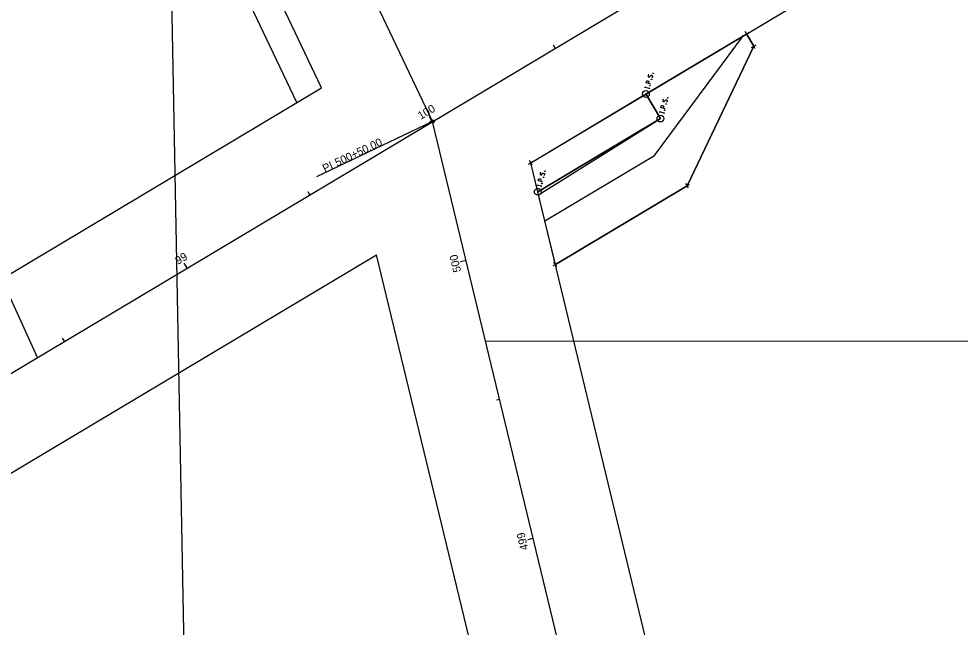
# Model space of a CAD drawing. Extents: x 2351593 to 2354159, y 766293 to 768001.
# Drawn here: x 2352271.1 to 2352600.5, y 766754.1 to 766966.8 of the extents above; entities that cross this region are included whole.
import ezdxf

# ---------------------------------------------------------------- set-up
doc = ezdxf.new("R2010")
doc.units = 0
for name, color, linetype in [('BD_X_Building', 7, 'Continuous'), ('PV_X_COP', 7, 'Continuous'), ('PV_X_Curb', 7, 'Continuous'), ('PV_X_Walk', 7, 'Continuous'), ('RD_X_Fence', 7, 'Continuous'), ('RD_X_Misc_Items', 7, 'Continuous'), ('SV_P_Mon_Cells_Set', 7, 'Continuous'), ('SV_X_Break_Lines', 7, 'Continuous'), ('SV_X_Mon_Cells_Found', 7, 'Continuous'), ('SV_X_Random_Point', 7, 'Continuous'), ('SV_X_Shot_Marker', 7, 'Continuous'), ('UT_X_Water_Cells', 7, 'Continuous'), ('VG_X_Cells', 7, 'Continuous'), ('VG_X_Flower_Bed', 7, 'Continuous'), ('VG_X_Shrub_Line_Lt', 7, 'Continuous')]:
    doc.layers.add(name, color=color, linetype=linetype)

msp = doc.modelspace()

# ---------------------------------------------------------------- linework, layer by layer
at = {"layer": 'BD_X_Building'}
for p, q in [((2352526.18, 766960.69), (2352525.21, 766962.31)), ((2352524.88, 766961.02), (2352526.5, 766961.99)), ((2352527.45, 766956.73), (2352529.07, 766957.69)), ((2352528.74, 766956.4), (2352527.77, 766958.02)), ((2352449.41, 766915.98), (2352451.03, 766916.95)), ((2352450.7, 766915.66), (2352449.73, 766917.28)), ((2352504.17, 766907.91), (2352505.8, 766908.87)), ((2352505.47, 766907.58), (2352504.5, 766909.2)), ((2352458.03, 766880.37), (2352459.65, 766881.33)), ((2352459.32, 766880.04), (2352458.35, 766881.66))]:
    msp.add_line(p, q, dxfattribs=at)
at = {"layer": 'PV_X_COP'}
for p, q in [((2352277.6, 766848.4), (2352192.4, 767035.46)), ((2352434.4, 766854.25), (2352921.95, 766853.61))]:
    msp.add_line(p, q, dxfattribs=at)
at = {"layer": 'PV_X_Curb'}
msp.add_line((2352337.69, 766292.88), (2352321.61, 767128.88), dxfattribs=at)
at = {"layer": 'PV_X_Walk'}
msp.add_line((2352415.86, 766930.9), (2352375.23, 766911.56), dxfattribs=at)
msp.add_circle((2352415.86, 766930.9), 0.6, dxfattribs=at)
at = {"layer": 'RD_X_Fence'}
for p, q in [((2352450.22, 766916.47), (2352490.49, 766940.49)), ((2352490.49, 766940.49), (2352495.61, 766931.91)), ((2352495.61, 766931.91), (2352452.68, 766906.29)), ((2352452.68, 766906.29), (2352450.22, 766916.47))]:
    msp.add_line(p, q, dxfattribs=at)
at = {"layer": 'RD_X_Misc_Items'}
for p, q in [((2352450.22, 766916.47), (2354158.95, 767936.09)), ((2352377.03, 766942.67), (2352291.74, 767121.83)), ((2351599.99, 766478.99), (2352377.03, 766942.67)), ((2352567.24, 766432.73), (2352450.22, 766916.47)), ((2352570.31, 766420.05), (2352450.22, 766916.47)), ((2351632.95, 766428.79), (2352396.27, 766884.28)), ((2352508.92, 766418.63), (2352396.27, 766884.28))]:
    msp.add_line(p, q, dxfattribs=at)
at = {"layer": 'SV_P_Mon_Cells_Set'}
for p, q in [((2352458.8, 766956.52), (2352458.18, 766957.55)), ((2352415.86, 766930.9), (2352414.84, 766932.62)), ((2352415.86, 766930.9), (2352414.69, 766930.62)), ((2352372.92, 766905.28), (2352372.31, 766906.31)), ((2352329.99, 766879.66), (2352328.96, 766881.38)), ((2352427.62, 766882.3), (2352425.67, 766881.83)), ((2352287.05, 766854.04), (2352286.43, 766855.07)), ((2352439.37, 766833.7), (2352438.21, 766833.42)), ((2352451.13, 766785.11), (2352449.19, 766784.64))]:
    msp.add_line(p, q, dxfattribs=at)
at = {"layer": 'SV_X_Break_Lines'}
msp.add_line((2352415.86, 766930.9), (2352375.23, 766911.56), dxfattribs=at)
msp.add_circle((2352415.86, 766930.9), 0.6, dxfattribs=at)
at = {"layer": 'SV_X_Mon_Cells_Found'}
for p, q in [((2351616.47, 766453.89), (2354143.58, 767961.85)), ((2352415.86, 766930.9), (2352321.61, 767128.88)), ((2352538.08, 766425.68), (2352415.86, 766930.9))]:
    msp.add_line(p, q, dxfattribs=at)
at = {"layer": 'SV_X_Random_Point'}
for p, q in [((2352528.26, 766957.21), (2352525.69, 766961.5)), ((2352504.98, 766908.39), (2352528.26, 766957.21)), ((2352458.83, 766880.85), (2352504.98, 766908.39))]:
    msp.add_line(p, q, dxfattribs=at)
at = {"layer": 'SV_X_Shot_Marker'}
for p, q in [((2352415.86, 766930.9), (2352414.84, 766932.62)), ((2352329.99, 766879.66), (2352329.37, 766880.69)), ((2352427.62, 766882.3), (2352425.67, 766881.83)), ((2352451.13, 766785.11), (2352449.96, 766784.82))]:
    msp.add_line(p, q, dxfattribs=at)
at = {"layer": 'UT_X_Water_Cells'}
for p, q in [((2352368.41, 766937.52), (2352281.78, 767119.48)), ((2352493.5, 766919), (2352524.71, 766960.92)), ((2352455.14, 766896.11), (2352493.5, 766919))]:
    msp.add_line(p, q, dxfattribs=at)
at = {"layer": 'VG_X_Cells'}
for p, q in [((2352495.61, 766931.91), (2352490.49, 766940.49)), ((2352452.68, 766906.29), (2352495.61, 766931.91))]:
    msp.add_line(p, q, dxfattribs=at)
at = {"layer": 'VG_X_Flower_Bed'}
for p, q in [((2352490.49, 766940.49), (2352525.69, 766961.5)), ((2352525.69, 766961.5), (2352528.26, 766957.21)), ((2352528.26, 766957.21), (2352504.98, 766908.39)), ((2352495.61, 766931.91), (2352490.49, 766940.49)), ((2352452.93, 766905.27), (2352495.61, 766931.91)), ((2352504.98, 766908.39), (2352458.84, 766880.85)), ((2352458.84, 766880.85), (2352452.93, 766905.27))]:
    msp.add_line(p, q, dxfattribs=at)
at = {"layer": 'VG_X_Shrub_Line_Lt'}
for points in [[(2352491.48, 766947.23), (2352491.45, 766947.21), (2352491.41, 766947.19), (2352491.35, 766947.1), (2352491.3, 766946.99), (2352491.28, 766946.9), (2352491.27, 766946.87), (2352491.27, 766946.72), (2352491.31, 766946.59), (2352491.39, 766946.49), (2352491.48, 766946.44), (2352491.56, 766946.42), (2352491.66, 766946.42), (2352491.77, 766946.48), (2352492.28, 766946.98), (2352492.35, 766947.02), (2352492.4, 766947.03), (2352492.48, 766947.03), (2352492.55, 766947.01), (2352492.62, 766946.98), (2352492.67, 766946.96), (2352492.72, 766946.92), (2352492.77, 766946.89), (2352492.8, 766946.86), (2352492.83, 766946.82), (2352492.84, 766946.78), (2352492.86, 766946.73), (2352492.86, 766946.7), (2352492.85, 766946.6), (2352492.81, 766946.45), (2352492.76, 766946.36), (2352492.64, 766946.24), (2352492.55, 766946.17)], [(2352492.91, 766947.71), (2352492.92, 766947.76), (2352492.96, 766947.79), (2352493.01, 766947.81), (2352493.07, 766947.79), (2352493.11, 766947.75), (2352493.13, 766947.71), (2352493.12, 766947.65), (2352493.08, 766947.63), (2352493.03, 766947.61), (2352492.97, 766947.62), (2352492.93, 766947.67), (2352492.91, 766947.71)], [(2352490.2, 766942.65), (2352490.29, 766942.99)], [(2352491.8, 766942.43), (2352490.25, 766942.82)], [(2352492.18, 766943.95), (2352490.63, 766944.34), (2352490.76, 766944.85), (2352490.78, 766944.9), (2352490.83, 766944.97), (2352490.86, 766945), (2352490.89, 766945.02), (2352490.96, 766945.05), (2352491.03, 766945.06), (2352491.14, 766945.06), (2352491.28, 766945.02), (2352491.33, 766945), (2352491.4, 766944.96), (2352491.47, 766944.9), (2352491.5, 766944.85), (2352491.51, 766944.81), (2352491.53, 766944.75), (2352491.52, 766944.66), (2352491.39, 766944.15)], [(2352491.75, 766942.26), (2352491.84, 766942.6)], [(2352491.82, 766943.41), (2352491.84, 766943.46), (2352491.87, 766943.49), (2352491.93, 766943.51), (2352491.99, 766943.49), (2352492.03, 766943.45), (2352492.05, 766943.41), (2352492.03, 766943.36), (2352492, 766943.33), (2352491.94, 766943.31), (2352491.88, 766943.33), (2352491.84, 766943.37), (2352491.82, 766943.41)], [(2352492.37, 766945.59), (2352492.39, 766945.64), (2352492.42, 766945.67), (2352492.48, 766945.69), (2352492.54, 766945.67), (2352492.58, 766945.63), (2352492.6, 766945.59), (2352492.58, 766945.54), (2352492.55, 766945.51), (2352492.49, 766945.49), (2352492.43, 766945.51), (2352492.39, 766945.55), (2352492.37, 766945.59)], [(2352498.03, 766939.12), (2352498.05, 766939.17), (2352498.08, 766939.2), (2352498.14, 766939.22), (2352498.2, 766939.2), (2352498.24, 766939.16), (2352498.25, 766939.12), (2352498.24, 766939.07), (2352498.21, 766939.04), (2352498.15, 766939.02), (2352498.09, 766939.04), (2352498.05, 766939.08), (2352498.03, 766939.12)], [(2352497.3, 766935.36), (2352495.75, 766935.75), (2352495.88, 766936.26), (2352495.91, 766936.31), (2352495.95, 766936.38), (2352495.98, 766936.41), (2352496.02, 766936.43), (2352496.09, 766936.46), (2352496.16, 766936.48), (2352496.26, 766936.47), (2352496.41, 766936.44), (2352496.45, 766936.41), (2352496.52, 766936.37), (2352496.6, 766936.31), (2352496.62, 766936.26), (2352496.64, 766936.22), (2352496.65, 766936.16), (2352496.64, 766936.07), (2352496.51, 766935.56)], [(2352496.6, 766938.64), (2352496.57, 766938.62), (2352496.54, 766938.6), (2352496.48, 766938.51), (2352496.42, 766938.4), (2352496.4, 766938.31), (2352496.39, 766938.28), (2352496.39, 766938.13), (2352496.44, 766938), (2352496.52, 766937.9), (2352496.61, 766937.85), (2352496.68, 766937.83), (2352496.79, 766937.83), (2352496.89, 766937.89), (2352497.41, 766938.39), (2352497.47, 766938.43), (2352497.52, 766938.44), (2352497.6, 766938.44), (2352497.68, 766938.42), (2352497.75, 766938.4), (2352497.79, 766938.37), (2352497.85, 766938.34), (2352497.89, 766938.3), (2352497.92, 766938.27), (2352497.95, 766938.23), (2352497.97, 766938.19), (2352497.98, 766938.14), (2352497.99, 766938.11), (2352497.97, 766938.01), (2352497.94, 766937.86), (2352497.89, 766937.77), (2352497.77, 766937.65), (2352497.67, 766937.58)], [(2352497.5, 766937), (2352497.51, 766937.06), (2352497.54, 766937.08), (2352497.6, 766937.1), (2352497.66, 766937.09), (2352497.7, 766937.04), (2352497.72, 766937), (2352497.71, 766936.95), (2352497.67, 766936.92), (2352497.62, 766936.9), (2352497.56, 766936.92), (2352497.52, 766936.96), (2352497.5, 766937)], [(2352495.33, 766934.06), (2352495.41, 766934.4)], [(2352496.92, 766933.84), (2352495.37, 766934.23)], [(2352496.88, 766933.67), (2352496.96, 766934.01)], [(2352496.95, 766934.82), (2352496.96, 766934.88), (2352496.99, 766934.9), (2352497.05, 766934.92), (2352497.11, 766934.91), (2352497.15, 766934.86), (2352497.17, 766934.82), (2352497.16, 766934.77), (2352497.12, 766934.74), (2352497.07, 766934.72), (2352497.01, 766934.74), (2352496.96, 766934.78), (2352496.95, 766934.82)], [(2352453.67, 766913.02), (2352453.64, 766913.01), (2352453.61, 766912.98), (2352453.55, 766912.89), (2352453.49, 766912.78), (2352453.47, 766912.7), (2352453.46, 766912.67), (2352453.46, 766912.52), (2352453.51, 766912.38), (2352453.59, 766912.28), (2352453.68, 766912.24), (2352453.75, 766912.22), (2352453.86, 766912.21), (2352453.96, 766912.28), (2352454.48, 766912.77), (2352454.54, 766912.81), (2352454.59, 766912.82), (2352454.67, 766912.83), (2352454.75, 766912.81), (2352454.82, 766912.78), (2352454.86, 766912.76), (2352454.92, 766912.72), (2352454.96, 766912.68), (2352454.99, 766912.65), (2352455.02, 766912.61), (2352455.04, 766912.57), (2352455.05, 766912.53), (2352455.06, 766912.49), (2352455.04, 766912.39), (2352455.01, 766912.24), (2352454.96, 766912.15), (2352454.84, 766912.03), (2352454.74, 766911.97)], [(2352455.1, 766913.5), (2352455.12, 766913.56), (2352455.15, 766913.58), (2352455.21, 766913.6), (2352455.27, 766913.59), (2352455.31, 766913.54), (2352455.32, 766913.5), (2352455.31, 766913.45), (2352455.28, 766913.42), (2352455.22, 766913.4), (2352455.16, 766913.42), (2352455.12, 766913.46), (2352455.1, 766913.5)], [(2352454.37, 766909.74), (2352452.82, 766910.13), (2352452.95, 766910.65), (2352452.98, 766910.7), (2352453.02, 766910.76), (2352453.05, 766910.79), (2352453.09, 766910.82), (2352453.16, 766910.84), (2352453.23, 766910.86), (2352453.33, 766910.86), (2352453.48, 766910.82), (2352453.52, 766910.8), (2352453.59, 766910.76), (2352453.67, 766910.69), (2352453.69, 766910.64), (2352453.71, 766910.6), (2352453.72, 766910.54), (2352453.71, 766910.45), (2352453.58, 766909.94)], [(2352454.57, 766911.39), (2352454.58, 766911.44), (2352454.61, 766911.47), (2352454.67, 766911.48), (2352454.73, 766911.47), (2352454.77, 766911.42), (2352454.79, 766911.39), (2352454.78, 766911.33), (2352454.74, 766911.31), (2352454.69, 766911.29), (2352454.63, 766911.3), (2352454.58, 766911.35), (2352454.57, 766911.39)], [(2352452.4, 766908.44), (2352452.48, 766908.79)], [(2352453.99, 766908.22), (2352452.44, 766908.61)], [(2352453.95, 766908.05), (2352454.03, 766908.39)], [(2352454.02, 766909.21), (2352454.03, 766909.26), (2352454.06, 766909.28), (2352454.12, 766909.3), (2352454.18, 766909.29), (2352454.22, 766909.24), (2352454.24, 766909.21), (2352454.23, 766909.15), (2352454.19, 766909.13), (2352454.14, 766909.11), (2352454.07, 766909.12), (2352454.03, 766909.17), (2352454.02, 766909.21)]]:
    msp.add_lwpolyline(points, dxfattribs=at)
for centre in [(2352490.49, 766940.49), (2352495.61, 766931.91), (2352452.68, 766906.29)]:
    msp.add_circle(centre, 1.2, dxfattribs=at)

# ---------------------------------------------------------------- texts
at = {"layer": 'PV_X_Walk'}
for s, p in [('500+50.00', (2352382.5, 766915.07)), ('PI', (2352378.18, 766913.02))]:
    msp.add_text(s, height=2.8, rotation=25.4572, dxfattribs=at).set_placement(p)
at = {"layer": 'SV_P_Mon_Cells_Set'}
for s, rotation, p in [('100', 30.825, (2352411.74, 766931.41)), ('99', 30.825, (2352326.82, 766880.74)), ('500', 103.5994, (2352425.91, 766878.51)), ('499', 103.5994, (2352449.42, 766781.35))]:
    msp.add_text(s, height=2.8, rotation=rotation, dxfattribs=at).set_placement(p)
at = {"layer": 'SV_X_Break_Lines'}
for s, p in [('500+50.00', (2352382.5, 766915.07)), ('PI', (2352378.18, 766913.02))]:
    msp.add_text(s, height=2.8, rotation=25.4572, dxfattribs=at).set_placement(p)
at = {"layer": 'SV_X_Shot_Marker'}
for s, rotation, p in [('100', 30.825, (2352411.74, 766931.41)), ('500', 103.5994, (2352425.91, 766878.51))]:
    msp.add_text(s, height=2.8, rotation=rotation, dxfattribs=at).set_placement(p)

doc.saveas('drawing.dxf')
